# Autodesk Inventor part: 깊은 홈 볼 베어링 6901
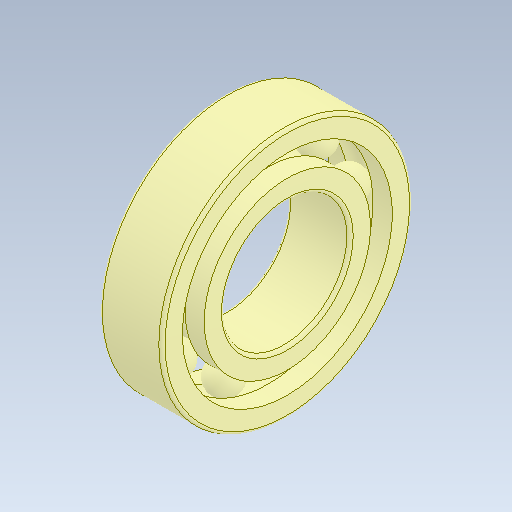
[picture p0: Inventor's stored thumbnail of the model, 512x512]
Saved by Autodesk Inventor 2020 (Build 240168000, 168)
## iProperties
Created: 2024-05
Part Number: 깊은 홈 볼 베어링 6901
Material: 강철, 연강
Description: 깊은 그루브 볼 베어링
Document SubType Name: Modeling
Designer: oem
Density: 7.85 g/cm^3
Appearance: 기본값
Author: jhkim
Sending System: Autodesk Inventor 2025
Preprocessor: ST-DEVELOPER v20
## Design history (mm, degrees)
feature "Solid1"
feature "Solid1:1"
feature "Solid1:2"
feature "Solid1:3"
feature "Solid1:4"
feature "Solid1:5"
feature "Solid1:6"
feature "Solid1:7"
feature "Solid1:8"
feature "Solid1:9"
feature "Solid1:10"
node "솔리드1"
node "솔리드2"
node "솔리드3"
node "솔리드4"
node "솔리드5"
node "솔리드6"
node "솔리드7"
node "솔리드8"
node "솔리드9"
node "솔리드10"
node "솔리드11"
